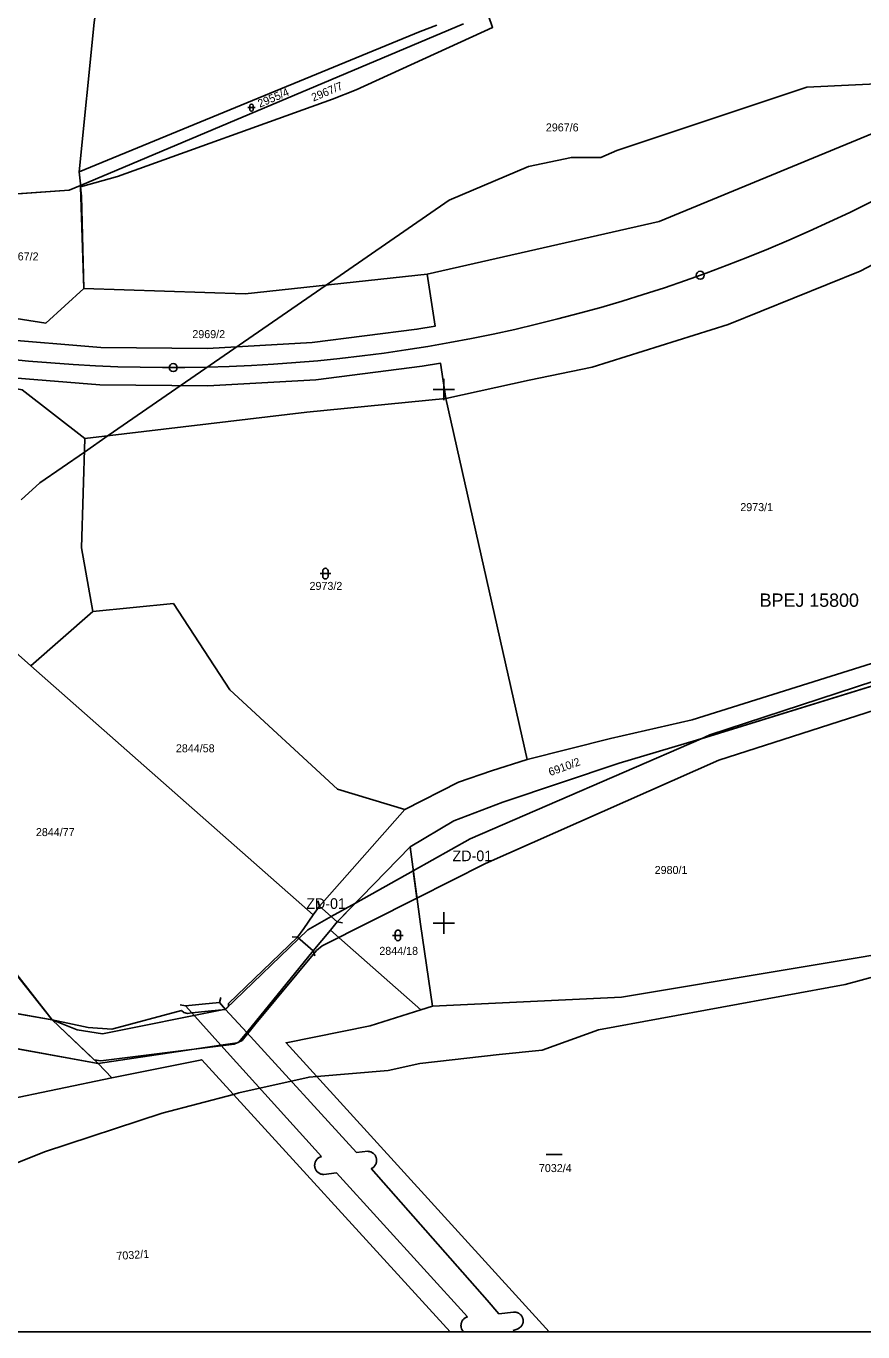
# Model space of a CAD drawing. Extents: x -800194 to -799297, y -1007177 to -1006761.
# Drawn here: x -799678.2 to -799521.5, y -1007176.6 to -1006931.9 of the extents above; entities that cross this region are included whole.
import ezdxf

# ---------------------------------------------------------------- set-up
doc = ezdxf.new("R2010")
doc.units = 0
for name, color, linetype in [('02_Osa_koleje', 7, 'Continuous'), ('_Vrstva 7 - Přesunutá', 7, 'Continuous'), ('BPEJ', 7, 'Continuous'), ('Dočasné zábory', 7, 'Continuous'), ('Dočasné zábory - čísla', 7, 'Continuous'), ('Legenda 1', 7, 'Continuous'), ('Pozemky SŽDC', 7, 'Continuous'), ('Ramove udaje', 7, 'Continuous'), ('Vrstva 53', 7, 'Continuous'), ('Vrstva 55', 7, 'Continuous'), ('Vrstva 56', 7, 'Continuous'), ('Vrstva 57', 7, 'Continuous'), ('Vrstva 58', 7, 'Continuous')]:
    doc.layers.add(name, color=color, linetype=linetype)

msp = doc.modelspace()

# ---------------------------------------------------------------- linework, layer by layer
at = {"layer": '02_Osa_koleje'}
msp.add_arc((-799651.02, -1006703.89), 292, 255.6249, 308.2052, dxfattribs=at)
at = {"layer": '_Vrstva 7 - Přesunutá'}
for centre in [(-799551.96, -1006978.57), (-799650.67, -1006995.89)]:
    msp.add_circle(centre, 0.75, dxfattribs=at)
at = {"layer": 'BPEJ'}
for points in [[(-799433.31, -1006923), (-799445.59, -1006934.44), (-799448.98, -1006934.86), (-799460.49, -1006939.26), (-799472.28, -1006943.76), (-799482.03, -1006946.72), (-799486.69, -1006947.15), (-799491.35, -1006948.42), (-799502.85, -1006945.54), (-799507.36, -1006944.41), (-799515.07, -1006942.49), (-799532.02, -1006943.33), (-799567.6, -1006955.2), (-799570.57, -1006956.47), (-799576.08, -1006956.47), (-799584.12, -1006958.16), (-799598.95, -1006964.52), (-799621.99, -1006980.43), (-799662.84, -1007008.64), (-799667.29, -1007011.71), (-799675.63, -1007017.47), (-799679.12, -1007020.67)], [(-799755.05, -1007176.65), (-799736.21, -1007167.44), (-799701.05, -1007153.46), (-799674.78, -1007142.87), (-799652.76, -1007135.67), (-799639.4, -1007132.13), (-799638.35, -1007131.86), (-799625.22, -1007128.89), (-799623.77, -1007128.77), (-799610.39, -1007127.62), (-799604.46, -1007126.35), (-799589.63, -1007124.66), (-799581.58, -1007123.81), (-799570.99, -1007120), (-799524.81, -1007111.52), (-799509.14, -1007107.29), (-799494.74, -1007104.74), (-799480.75, -1007102.63), (-799465.08, -1007100.08), (-799454.28, -1007099.52)]]:
    msp.add_lwpolyline(points, dxfattribs=at)
at = {"layer": 'Dočasné zábory'}
for points in [[(-799605.71, -1007090.19), (-799595.06, -1007084.22), (-799551.8, -1007065.45), (-799478.24, -1007042.75), (-799444.02, -1007032.78), (-799434.1, -1007028.26), (-799425.58, -1007022.42), (-799420, -1007017.54), (-799409.68, -1007006.29), (-799408.65, -1007008.83), (-799412.5, -1007010.44), (-799420, -1007017.54), (-799436.16, -1007033.34), (-799548.49, -1007069.46), (-799592.16, -1007088.85), (-799605.02, -1007095.33)], [(-799621.05, -1007098.8), (-799619.94, -1007099.79), (-799616.53, -1007096.26)]]:
    msp.add_lwpolyline(points, close=True, dxfattribs=at)
msp.add_lwpolyline([(-799478.24, -1007042.75), (-799551.8, -1007065.45), (-799550.16, -1007064.74), (-799440.86, -1007028.93)], dxfattribs=at)
at = {"layer": 'Legenda 1'}
msp.add_lwpolyline([(-800193.4, -1007176.65), (-799312.4, -1007176.65), (-799312.4, -1006766.65), (-800193.4, -1006766.65)], close=True, dxfattribs=at)
at = {"layer": 'Pozemky SŽDC'}
for points in [[(-799683.81, -1006990.52), (-799664.23, -1006992.09), (-799644.23, -1006992.31), (-799624.62, -1006991.18), (-799605.02, -1006988.7), (-799601.63, -1006988.13), (-799603.07, -1006978.39), (-799559.64, -1006968.48), (-799519.68, -1006952.01)], [(-799495.25, -1006963.74), (-799521.98, -1006977.8), (-799546.71, -1006987.83), (-799572.22, -1006995.8), (-799583.97, -1006998.26), (-799599.63, -1007001.65), (-799600.6, -1006995.06), (-799604.02, -1006995.63), (-799623.98, -1006998.15), (-799644.19, -1006999.31), (-799664.43, -1006999.09), (-799684.6, -1006997.48)]]:
    msp.add_lwpolyline(points, dxfattribs=at)
for points in [[(-799673.33, -1007118.14), (-799693.11, -1007093.25), (-799714.14, -1007072.19), (-799715.54, -1007076.14), (-799696.4, -1007096.25), (-799680.35, -1007116.92)], [(-799673.33, -1007118.14), (-799668.64, -1007120.02), (-799663.88, -1007120.77), (-799640.89, -1007116.14), (-799625.43, -1007101.26), (-799621.05, -1007098.8), (-799619.94, -1007099.79), (-799616.53, -1007096.26), (-799605.71, -1007090.19), (-799605.02, -1007095.33), (-799622.76, -1007104.28), (-799623.83, -1007105.16), (-799635.16, -1007118.86), (-799637.76, -1007122), (-799639.26, -1007122.74), (-799664.22, -1007125.86), (-799665.47, -1007125.65)]]:
    msp.add_lwpolyline(points, close=True, dxfattribs=at)
at = {"layer": 'Ramove udaje'}
for p, q in [((-799600, -1006998), (-799600, -1007002)), ((-799602, -1007000), (-799600, -1007000)), ((-799600, -1007000), (-799598, -1007000)), ((-799602, -1007100), (-799600, -1007100)), ((-799600, -1007098), (-799600, -1007102)), ((-799600, -1007100), (-799598, -1007100))]:
    msp.add_line(p, q, dxfattribs=at)
at = {"layer": 'Vrstva 53'}
for points in [[(-799831.75, -1006884.86), (-799830.3, -1006886.5), (-799824.73, -1006892.78), (-799821.02, -1006893.98), (-799817.05, -1006894.06), (-799808.6, -1006894.22), (-799715.17, -1006892.15), (-799698.08, -1006856.38), (-799691.64, -1006842.91), (-799685.69, -1006830.46), (-799684.1, -1006830.47), (-799704.46, -1006903.31), (-799691.31, -1006907.33), (-799679.26, -1006911.01), (-799685.71, -1006952.41), (-799686.25, -1006963.73), (-799670.17, -1006962.64), (-799668.03, -1006961.74), (-799668, -1006962.02), (-799667.43, -1006981.06), (-799637.16, -1006982.06), (-799603.07, -1006978.39), (-799559.64, -1006968.48), (-799519.68, -1006952.01)], [(-799495.25, -1006963.74), (-799521.98, -1006977.8), (-799546.71, -1006987.83), (-799572.22, -1006995.8), (-799583.97, -1006998.26), (-799599.63, -1007001.65), (-799584.37, -1007069.36), (-799591.04, -1007071.48), (-799597.25, -1007073.58), (-799607.27, -1007078.7), (-799623.27, -1007096.82), (-799619.94, -1007099.79), (-799606.31, -1007085.7), (-799604.36, -1007100.23), (-799602.09, -1007115.59), (-799604.31, -1007116.28), (-799613.8, -1007119.26), (-799629.52, -1007122.44), (-799580.26, -1007176.65)], [(-799713.93, -1007117.37), (-799664.74, -1007126.35), (-799673.33, -1007118.14), (-799714.71, -1007110.97)], [(-799598.82, -1007176.65), (-799645.33, -1007125.63), (-799662.13, -1007129.03), (-799692.74, -1007135.4)]]:
    msp.add_lwpolyline(points, dxfattribs=at)
at = {"layer": 'Vrstva 55'}
for p, q in [((-799668.25, -1006959.17), (-799604.43, -1006932.91)), ((-799596.27, -1006931.47), (-799668.03, -1006961.74)), ((-799604.43, -1006932.91), (-799601.26, -1006931.67)), ((-799668, -1006962.02), (-799668.03, -1006961.74)), ((-799599.63, -1007001.65), (-799584.37, -1007069.36)), ((-799700.54, -1007031.23), (-799677.3, -1007051.77)), ((-799677.3, -1007051.77), (-799665.73, -1007041.59)), ((-799712.65, -1007067.97), (-799673.33, -1007118.14)), ((-799623.27, -1007096.82), (-799607.27, -1007078.7)), ((-799606.31, -1007085.7), (-799619.94, -1007099.79)), ((-799619.94, -1007099.79), (-799623.27, -1007096.82)), ((-799673.33, -1007118.14), (-799714.71, -1007110.97)), ((-799613.8, -1007119.26), (-799604.31, -1007116.28)), ((-799604.31, -1007116.28), (-799602.09, -1007115.59)), ((-799713.93, -1007117.37), (-799664.74, -1007126.35)), ((-799673.33, -1007118.14), (-799664.74, -1007126.35)), ((-799664.74, -1007126.35), (-799662.13, -1007129.03))]:
    msp.add_line(p, q, dxfattribs=at)
for points in [[(-799652.26, -1006884.27), (-799656.47, -1006891.91), (-799662.36, -1006908.86), (-799665.44, -1006931.17), (-799668.25, -1006959.17)], [(-799591.61, -1006929.95), (-799590.84, -1006932.11), (-799616.41, -1006943.81), (-799620.83, -1006945.58), (-799661.1, -1006960.05), (-799668, -1006962.02)], [(-799667.43, -1006981.06), (-799637.16, -1006982.06), (-799603.07, -1006978.39), (-799559.64, -1006968.48), (-799519.68, -1006952.01)], [(-799668.03, -1006961.74), (-799668.05, -1006961.46), (-799668.25, -1006959.17)], [(-799599.63, -1007001.65), (-799583.97, -1006998.26), (-799572.22, -1006995.8), (-799546.71, -1006987.83), (-799521.98, -1006977.8), (-799495.25, -1006963.74), (-799489.22, -1006959.79), (-799487.22, -1006958.47)], [(-799686.25, -1006963.73), (-799681.51, -1006963.46), (-799670.17, -1006962.64), (-799668.03, -1006961.74)], [(-799667.43, -1006981.06), (-799667.85, -1006963.74), (-799668, -1006962.02)], [(-799691.32, -1006984.61), (-799685.35, -1006985.87), (-799674.55, -1006987.57), (-799667.43, -1006981.06)], [(-799667.22, -1007009.16), (-799678.94, -1007000.07), (-799720.83, -1006992.39), (-799728.88, -1006993.59), (-799733.28, -1006992.13)], [(-799667.22, -1007009.16), (-799625.65, -1007004.23), (-799599.63, -1007001.65)], [(-799409.68, -1007006.29), (-799420, -1007017.54), (-799425.58, -1007022.42), (-799434.1, -1007028.26), (-799444.02, -1007032.78), (-799478.24, -1007042.75), (-799552.64, -1007065.71), (-799567.11, -1007070.01), (-799588.9, -1007077.33), (-799598.09, -1007080.87), (-799606.31, -1007085.7)], [(-799665.73, -1007041.59), (-799667.81, -1007029.7), (-799667.22, -1007009.16)], [(-799584.37, -1007069.36), (-799568.78, -1007065.44), (-799553.44, -1007061.89), (-799480.9, -1007039.1), (-799478.14, -1007038.23)], [(-799607.27, -1007078.7), (-799619.88, -1007074.91), (-799640.06, -1007056.27), (-799650.63, -1007040.08), (-799665.73, -1007041.59)], [(-799677.3, -1007051.77), (-799624.44, -1007098.49), (-799623.27, -1007096.82)], [(-799607.27, -1007078.7), (-799597.25, -1007073.58), (-799591.04, -1007071.48), (-799584.37, -1007069.36)], [(-799602.09, -1007115.59), (-799604.36, -1007100.23), (-799606.31, -1007085.7)], [(-799602.09, -1007115.59), (-799566.73, -1007113.9), (-799505.74, -1007103.69), (-799454.59, -1007096.36)], [(-799604.31, -1007116.28), (-799621.22, -1007101.34), (-799619.94, -1007099.79)], [(-799580.26, -1007176.65), (-799629.52, -1007122.44), (-799613.8, -1007119.26)], [(-799598.82, -1007176.65), (-799645.33, -1007125.63), (-799662.13, -1007129.03)], [(-799662.13, -1007129.03), (-799692.74, -1007135.4), (-799710.71, -1007144.99), (-799727.84, -1007152.76)]]:
    msp.add_lwpolyline(points, dxfattribs=at)
at = {"layer": 'Vrstva 56'}
for p, q in [((-799623.58, -1007095.87), (-799623.27, -1007096.82)), ((-799624.44, -1007098.49), (-799626.23, -1007101.04)), ((-799618.96, -1007099.98), (-799619.94, -1007099.79)), ((-799628.37, -1007102.62), (-799627.37, -1007102.67)), ((-799626.23, -1007101.04), (-799627.37, -1007102.67)), ((-799624.45, -1007105.23), (-799621.22, -1007101.34)), ((-799640.29, -1007115.09), (-799627.37, -1007102.67)), ((-799627.37, -1007102.67), (-799624.45, -1007105.23)), ((-799636.89, -1007120.54), (-799624.45, -1007105.23)), ((-799624.14, -1007106.18), (-799624.45, -1007105.23)), ((-799641.73, -1007113.95), (-799641.97, -1007114.92)), ((-799649.14, -1007116.42), (-799662.13, -1007119.88)), ((-799649.34, -1007115.32), (-799648.37, -1007115.55)), ((-799648.66, -1007116.78), (-799649.14, -1007116.42)), ((-799647.98, -1007116.94), (-799648.66, -1007116.78)), ((-799648.37, -1007115.55), (-799645.26, -1007115.24)), ((-799648.37, -1007115.55), (-799647.19, -1007116.86)), ((-799647.98, -1007116.94), (-799647.19, -1007116.86)), ((-799647.19, -1007116.86), (-799644.09, -1007116.53)), ((-799647.19, -1007116.86), (-799641.73, -1007122.91)), ((-799645.26, -1007115.24), (-799641.97, -1007114.92)), ((-799644.09, -1007116.53), (-799640.86, -1007116.19)), ((-799641.97, -1007114.92), (-799640.86, -1007116.19)), ((-799640.86, -1007116.19), (-799640.3, -1007115.68)), ((-799636.89, -1007120.54), (-799640.86, -1007116.19)), ((-799640.3, -1007115.68), (-799640.29, -1007115.09)), ((-799666.59, -1007119.58), (-799673.33, -1007118.14)), ((-799662.13, -1007119.88), (-799666.59, -1007119.58)), ((-799638.42, -1007122.42), (-799636.89, -1007120.54)), ((-799616.33, -1007143.04), (-799636.89, -1007120.54)), ((-799664.74, -1007126.35), (-799641.73, -1007122.91)), ((-799641.73, -1007122.91), (-799638.71, -1007122.46)), ((-799641.73, -1007122.91), (-799622.9, -1007143.79)), ((-799638.71, -1007122.46), (-799638.42, -1007122.42)), ((-799614.21, -1007142.8), (-799616.33, -1007143.04)), ((-799613.58, -1007146.05), (-799591.84, -1007170.73)), ((-799622.43, -1007147.14), (-799620.11, -1007146.85)), ((-799620.11, -1007146.85), (-799595.55, -1007173.85)), ((-799591.84, -1007170.73), (-799589.67, -1007173.25)), ((-799589.67, -1007173.25), (-799586.91, -1007172.97)), ((-799586.99, -1007176.37), (-799586.23, -1007176.11)), ((-799586.99, -1007176.37), (-799586.72, -1007176.65))]:
    msp.add_line(p, q, dxfattribs=at)
for points in [[(-799622.43, -1007147.14), (-799622.55, -1007147.14), (-799622.66, -1007147.13), (-799622.78, -1007147.11), (-799622.89, -1007147.09), (-799623, -1007147.06), (-799623.11, -1007147.02), (-799623.21, -1007146.97), (-799623.32, -1007146.92), (-799623.42, -1007146.86), (-799623.51, -1007146.79), (-799623.6, -1007146.72), (-799623.68, -1007146.64), (-799623.76, -1007146.56), (-799623.83, -1007146.47), (-799623.9, -1007146.37), (-799623.96, -1007146.27), (-799624.01, -1007146.17), (-799624.06, -1007146.07), (-799624.1, -1007145.96), (-799624.13, -1007145.84), (-799624.15, -1007145.73), (-799624.17, -1007145.62), (-799624.18, -1007145.5), (-799624.18, -1007145.39), (-799624.17, -1007145.27), (-799624.16, -1007145.16), (-799624.13, -1007145.04), (-799624.1, -1007144.93), (-799624.07, -1007144.82), (-799624.02, -1007144.72), (-799623.97, -1007144.61), (-799623.91, -1007144.52), (-799623.84, -1007144.42), (-799623.77, -1007144.33), (-799623.69, -1007144.24), (-799623.61, -1007144.17), (-799623.52, -1007144.09), (-799623.43, -1007144.03), (-799623.33, -1007143.96), (-799623.22, -1007143.91), (-799623.12, -1007143.86), (-799623.01, -1007143.82), (-799622.9, -1007143.79)], [(-799613.58, -1007146.05), (-799613.48, -1007146), (-799613.38, -1007145.94), (-799613.28, -1007145.88), (-799613.19, -1007145.81), (-799613.11, -1007145.74), (-799613.03, -1007145.66), (-799612.95, -1007145.57), (-799612.88, -1007145.48), (-799612.82, -1007145.38), (-799612.76, -1007145.28), (-799612.71, -1007145.18), (-799612.67, -1007145.07), (-799612.64, -1007144.97), (-799612.61, -1007144.85), (-799612.59, -1007144.74), (-799612.58, -1007144.63), (-799612.57, -1007144.52), (-799612.57, -1007144.4), (-799612.58, -1007144.29), (-799612.6, -1007144.17), (-799612.63, -1007144.06), (-799612.66, -1007143.95), (-799612.7, -1007143.85), (-799612.75, -1007143.74), (-799612.8, -1007143.64), (-799612.86, -1007143.55), (-799612.93, -1007143.45), (-799613, -1007143.36), (-799613.08, -1007143.28), (-799613.17, -1007143.21), (-799613.25, -1007143.14), (-799613.35, -1007143.07), (-799613.45, -1007143.01), (-799613.55, -1007142.96), (-799613.65, -1007142.91), (-799613.76, -1007142.88), (-799613.87, -1007142.85), (-799613.98, -1007142.82), (-799614.1, -1007142.81), (-799614.21, -1007142.8)], [(-799586.91, -1007172.97), (-799586.8, -1007172.96), (-799586.69, -1007172.96), (-799586.57, -1007172.97), (-799586.46, -1007172.98), (-799586.35, -1007173.01), (-799586.24, -1007173.04), (-799586.14, -1007173.08), (-799586.03, -1007173.12), (-799585.93, -1007173.17), (-799585.84, -1007173.23), (-799585.74, -1007173.3), (-799585.66, -1007173.37), (-799585.58, -1007173.45), (-799585.5, -1007173.53), (-799585.43, -1007173.62), (-799585.37, -1007173.71), (-799585.31, -1007173.81), (-799585.26, -1007173.91), (-799585.22, -1007174.02), (-799585.18, -1007174.12), (-799585.16, -1007174.23), (-799585.14, -1007174.34), (-799585.12, -1007174.46), (-799585.12, -1007174.57), (-799585.12, -1007174.68), (-799585.13, -1007174.79), (-799585.15, -1007174.91), (-799585.18, -1007175.02), (-799585.21, -1007175.12), (-799585.26, -1007175.23), (-799585.31, -1007175.33), (-799585.36, -1007175.43), (-799585.42, -1007175.52), (-799585.49, -1007175.61), (-799585.57, -1007175.69), (-799585.65, -1007175.77), (-799585.73, -1007175.84), (-799585.83, -1007175.91), (-799585.92, -1007175.97), (-799586.02, -1007176.03), (-799586.12, -1007176.07), (-799586.23, -1007176.11)], [(-799596.25, -1007176.65), (-799596.26, -1007176.64), (-799596.34, -1007176.56), (-799596.41, -1007176.47), (-799596.48, -1007176.38), (-799596.54, -1007176.29), (-799596.59, -1007176.19), (-799596.64, -1007176.09), (-799596.68, -1007175.98), (-799596.71, -1007175.87), (-799596.74, -1007175.76), (-799596.76, -1007175.65), (-799596.77, -1007175.54), (-799596.77, -1007175.43), (-799596.76, -1007175.32), (-799596.75, -1007175.2), (-799596.73, -1007175.09), (-799596.7, -1007174.98), (-799596.67, -1007174.88), (-799596.63, -1007174.77), (-799596.58, -1007174.67), (-799596.52, -1007174.57), (-799596.46, -1007174.48), (-799596.39, -1007174.39), (-799596.31, -1007174.31), (-799596.23, -1007174.23), (-799596.15, -1007174.15), (-799596.06, -1007174.09), (-799595.96, -1007174.03), (-799595.86, -1007173.97), (-799595.76, -1007173.92), (-799595.66, -1007173.88), (-799595.55, -1007173.85)]]:
    msp.add_lwpolyline(points, dxfattribs=at)
at = {"layer": 'Vrstva 58'}
for p, q in [((-799636.67, -1006947.15), (-799635.33, -1006947.15)), ((-799636.33, -1006946.82), (-799636.33, -1006947.49)), ((-799635.67, -1006947.49), (-799635.67, -1006946.82)), ((-799622.66, -1007034.01), (-799622.66, -1007035.01)), ((-799621.66, -1007035.01), (-799621.66, -1007034.01)), ((-799623.16, -1007034.51), (-799621.16, -1007034.51)), ((-799609.58, -1007102.33), (-799607.58, -1007102.33)), ((-799609.08, -1007101.83), (-799609.08, -1007102.84)), ((-799608.08, -1007102.84), (-799608.08, -1007101.83)), ((-799580.84, -1007143.4), (-799577.84, -1007143.4))]:
    msp.add_line(p, q, dxfattribs=at)
for centre, radius, start, end in [((-799636, -1006946.82), 0.335, 0, 180), ((-799636, -1006947.49), 0.335, 180, 359.9879), ((-799622.16, -1007034.01), 0.5, 0, 180), ((-799622.16, -1007035.01), 0.5, 180, 359.9879), ((-799608.58, -1007101.83), 0.5, 0, 180), ((-799608.58, -1007102.83), 0.5, 180, 359.9879)]:
    msp.add_arc(centre, radius, start, end, dxfattribs=at)

# ---------------------------------------------------------------- texts
at = {"layer": 'BPEJ'}
msp.add_text('BPEJ 15800', height=2.5, dxfattribs=at).set_placement((-799540.82, -1007040.73))
at = {"layer": 'Dočasné zábory - čísla'}
for p in [(-799598.35, -1007088.41), (-799625.75, -1007097.36)]:
    msp.add_text('ZD-01', height=2, rotation=0, dxfattribs=at).set_placement(p)
at = {"layer": 'Vrstva 57'}
for s, rotation, p in [('2955/4', 23, (-799634.45, -1006947.18)), ('2967/7', 23, (-799624.4, -1006946.03)), ('6910/2', 20, (-799580.05, -1007072.47)), ('7032/1', 4, (-799661.25, -1007163.18))]:
    msp.add_text(s, height=1.5, rotation=rotation, dxfattribs=at).set_placement(p)
for s, p in [('2967/6', (-799580.87, -1006951.61)), ('2967/2', (-799682.02, -1006975.79)), ('2969/2', (-799647.08, -1006990.36)), ('2973/1', (-799544.45, -1007022.79)), ('2973/2', (-799625.13, -1007037.56)), ('2844/58', (-799650.16, -1007068)), ('2844/77', (-799676.38, -1007083.71)), ('2980/1', (-799560.49, -1007090.81)), ('2844/18', (-799612.06, -1007105.97)), ('7032/4', (-799582.17, -1007146.69))]:
    msp.add_text(s, height=1.5, dxfattribs=at).set_placement(p)

doc.saveas('drawing.dxf')
